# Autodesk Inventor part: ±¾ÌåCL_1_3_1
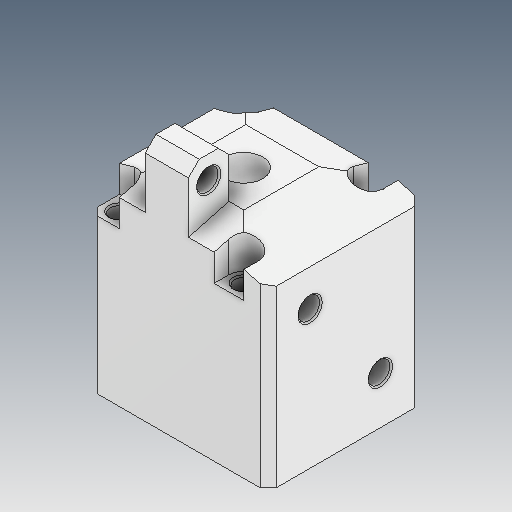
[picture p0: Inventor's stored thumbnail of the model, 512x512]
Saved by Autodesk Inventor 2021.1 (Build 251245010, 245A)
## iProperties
Created: 2021-05
Part Number: ±¾ÌåCL_1_3_1
Material: Ogólny
Document SubType Name: Modeling
Designer: user
Density: 1 g/cm^3
Appearance: Domyślna
Author: user
Revision Number: ÈÎºÎ
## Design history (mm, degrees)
feature "ÊäÈë1"
node "Bryła1"
